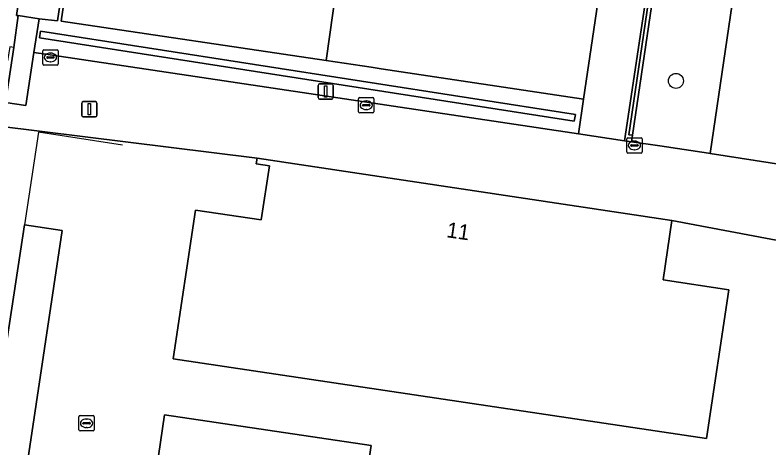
# Model space of a CAD drawing. Extents: x 161090 to 161692, y 379509 to 380907.
# Drawn here: x 161242.72 to 161291.79, y 380401.2 to 380429.41 of the extents above; entities that cross this region are included whole.
import ezdxf

# ---------------------------------------------------------------- set-up
doc = ezdxf.new("R2010")
doc.units = 0
for name, color, linetype in [('IMGEO_Boom', 7, 'Continuous'), ('IMGEO_Groenvoorziening', 7, 'Continuous'), ('IMGEO_Haag', 7, 'Continuous'), ('IMGEO_Kolk', 7, 'Continuous'), ('IMGEO_Lichtmast', 7, 'Continuous'), ('IMGEO_Muur', 7, 'Continuous'), ('IMGEO_Pand', 7, 'Continuous'), ('IMGEO_Pand_nummerreeks', 7, 'Continuous'), ('IMGEO_Rijbaan_lokaal_open', 7, 'Continuous'), ('IMGEO_Terreindeel_halfverhard', 7, 'Continuous'), ('IMGEO_Voetpad_gesloten', 7, 'Continuous'), ('IMGEO_Voetpad_open', 7, 'Continuous')]:
    doc.layers.add(name, color=color, linetype=linetype)

msp = doc.modelspace()

# ---------------------------------------------------------------- linework, layer by layer
at = {"layer": 'IMGEO_Boom'}
msp.add_circle((161285.743, 380425.117), 0.489, dxfattribs=at)
at = {"layer": 'IMGEO_Groenvoorziening'}
for points in [[(161288.546, 380459.846), (161288.807, 380461.604), (161214.037, 380472.701), (161213.983, 380472.328), (161288.498, 380461.269), (161288.271, 380459.723), (161282.68, 380421.608), (161282.918, 380421.573)], [(161244.371, 380428.365), (161244.302, 380427.924), (161279.123, 380422.484), (161279.192, 380422.925)], [(161279.192, 380422.925), (161279.123, 380422.484), (161244.302, 380427.924), (161244.371, 380428.365)], [(161265.895, 380401.354), (161252.452, 380403.361), (161250.511, 380390.143), (161263.942, 380388.053), (161264.811, 380394.143), (161265.201, 380396.75)]]:
    msp.add_lwpolyline(points, close=True, dxfattribs=at)
for points in [[(161242.631, 380427.302), (161242.91, 380429.37), (161242.819, 380429.374), (161248.213, 380465.672)], [(161250.851, 380465.255), (161245.479, 380429.036), (161244.277, 380429.158), (161243.941, 380426.968), (161244.715, 380426.852), (161279.388, 380421.67), (161279.724, 380423.935), (161266.543, 380425.906), (161265.906, 380426.002), (161262.978, 380426.44), (161245.726, 380429.02), (161251.106, 380465.29)], [(161286.723, 380450.172), (161282.385, 380421.222), (161282.856, 380421.152), (161282.918, 380421.573), (161282.68, 380421.608), (161288.271, 380459.723)]]:
    msp.add_lwpolyline(points, dxfattribs=at)
at = {"layer": 'IMGEO_Haag'}
for points in [[(161214.037, 380472.701), (161213.983, 380472.328), (161288.498, 380461.269), (161288.271, 380459.723), (161282.68, 380421.608), (161282.918, 380421.573), (161288.546, 380459.846), (161288.807, 380461.604)], [(161244.371, 380428.365), (161244.302, 380427.924), (161279.123, 380422.484), (161279.192, 380422.925)]]:
    msp.add_lwpolyline(points, close=True, dxfattribs=at)
at = {"layer": 'IMGEO_Kolk'}
for p, q in [((161244.519, 380426.221), (161244.519, 380427.073)), ((161244.594, 380427.147), (161245.446, 380427.147)), ((161245.52, 380427.073), (161245.52, 380426.221)), ((161244.778, 380426.641), (161244.778, 380426.653)), ((161245.216, 380426.604), (161244.818, 380426.604)), ((161244.821, 380426.69), (161245.219, 380426.69)), ((161245.007, 380426.927), (161245.032, 380426.927)), ((161245.262, 380426.653), (161245.262, 380426.641)), ((161245.446, 380426.147), (161244.594, 380426.147)), ((161245.03, 380426.367), (161245.005, 380426.367)), ((161265.153, 380424.03), (161266.005, 380424.03)), ((161265.078, 380423.104), (161265.078, 380423.956)), ((161265.337, 380423.524), (161265.337, 380423.536)), ((161265.38, 380423.573), (161265.778, 380423.573)), ((161265.566, 380423.81), (161265.591, 380423.81)), ((161265.821, 380423.536), (161265.821, 380423.524)), ((161266.079, 380423.956), (161266.079, 380423.104)), ((161266.005, 380423.03), (161265.153, 380423.03)), ((161265.775, 380423.487), (161265.377, 380423.487)), ((161265.589, 380423.25), (161265.564, 380423.25)), ((161282.541, 380420.488), (161282.541, 380421.34)), ((161282.616, 380421.414), (161283.468, 380421.414)), ((161283.029, 380421.194), (161283.054, 380421.194)), ((161283.542, 380421.34), (161283.542, 380420.488)), ((161282.8, 380420.908), (161282.8, 380420.92)), ((161283.238, 380420.871), (161282.84, 380420.871)), ((161282.843, 380420.957), (161283.241, 380420.957)), ((161283.052, 380420.634), (161283.027, 380420.634)), ((161283.284, 380420.92), (161283.284, 380420.908)), ((161283.468, 380420.414), (161282.616, 380420.414)), ((161246.868, 380402.38), (161246.868, 380403.232)), ((161246.943, 380403.306), (161247.795, 380403.306)), ((161247.356, 380403.086), (161247.381, 380403.086)), ((161247.869, 380403.232), (161247.869, 380402.38)), ((161247.127, 380402.8), (161247.127, 380402.812)), ((161247.565, 380402.763), (161247.167, 380402.763)), ((161247.17, 380402.849), (161247.568, 380402.849)), ((161247.379, 380402.526), (161247.354, 380402.526)), ((161247.611, 380402.812), (161247.611, 380402.8)), ((161247.795, 380402.306), (161246.943, 380402.306))]:
    msp.add_line(p, q, dxfattribs=at)
for points in [[(161244.519, 380426.221), (161244.519, 380427.073)], [(161244.594, 380427.147), (161245.446, 380427.147)], [(161245.52, 380427.073), (161245.52, 380426.221)], [(161245.446, 380426.147), (161244.594, 380426.147)], [(161265.153, 380424.03), (161266.005, 380424.03)], [(161265.078, 380423.104), (161265.078, 380423.956)], [(161266.079, 380423.956), (161266.079, 380423.104)], [(161266.005, 380423.03), (161265.153, 380423.03)], [(161282.541, 380420.488), (161282.541, 380421.34)], [(161282.616, 380421.414), (161283.468, 380421.414)], [(161283.542, 380421.34), (161283.542, 380420.488)], [(161283.468, 380420.414), (161282.616, 380420.414)], [(161246.868, 380402.38), (161246.868, 380403.232)], [(161246.943, 380403.306), (161247.795, 380403.306)], [(161247.869, 380403.232), (161247.869, 380402.38)], [(161247.795, 380402.306), (161246.943, 380402.306)]]:
    msp.add_lwpolyline(points, dxfattribs=at)
for centre, radius, start, end in [((161244.596, 380427.071), 0.0765, 91.552, 178.448), ((161244.596, 380427.071), 0.0765, 91.552, 178.448), ((161245.444, 380427.071), 0.0765, 1.552, 88.448), ((161245.444, 380427.071), 0.0765, 1.552, 88.448), ((161244.818, 380426.65), 0.0403, 85.8775, 175.7526), ((161244.815, 380426.64), 0.0366, 178.938, 274.7102), ((161245.219, 380426.647), 0.043, 264.8664, 352.4533), ((161245.223, 380426.652), 0.0386, 1.7309, 96.639), ((161244.596, 380426.223), 0.0765, 181.552, 268.448), ((161244.596, 380426.223), 0.0765, 181.552, 268.448), ((161245.444, 380426.223), 0.0765, 271.552, 358.448), ((161245.444, 380426.223), 0.0765, 271.552, 358.448), ((161265.155, 380423.954), 0.0765, 91.552, 178.448), ((161265.155, 380423.954), 0.0765, 91.552, 178.448), ((161266.003, 380423.954), 0.0765, 1.552, 88.448), ((161266.003, 380423.954), 0.0765, 1.552, 88.448), ((161265.377, 380423.533), 0.0403, 85.8775, 175.7526), ((161265.374, 380423.523), 0.0366, 178.938, 274.7102), ((161265.778, 380423.53), 0.043, 264.8664, 352.4533), ((161265.782, 380423.535), 0.0386, 1.7309, 96.639), ((161265.155, 380423.106), 0.0765, 181.552, 268.448), ((161265.155, 380423.106), 0.0765, 181.552, 268.448), ((161266.003, 380423.106), 0.0765, 271.552, 358.448), ((161266.003, 380423.106), 0.0765, 271.552, 358.448), ((161282.618, 380421.338), 0.0765, 91.552, 178.448), ((161282.618, 380421.338), 0.0765, 91.552, 178.448), ((161283.466, 380421.338), 0.0765, 1.552, 88.448), ((161283.466, 380421.338), 0.0765, 1.552, 88.448), ((161282.84, 380420.917), 0.0403, 85.8775, 175.7526), ((161282.837, 380420.907), 0.0366, 178.938, 274.7102), ((161283.241, 380420.914), 0.043, 264.8664, 352.4533), ((161283.245, 380420.919), 0.0386, 1.7309, 96.639), ((161282.618, 380420.49), 0.0765, 181.552, 268.448), ((161282.618, 380420.49), 0.0765, 181.552, 268.448), ((161283.466, 380420.49), 0.0765, 271.552, 358.448), ((161283.466, 380420.49), 0.0765, 271.552, 358.448), ((161246.945, 380403.23), 0.0765, 91.552, 178.448), ((161246.945, 380403.23), 0.0765, 91.552, 178.448), ((161247.793, 380403.23), 0.0765, 1.552, 88.448), ((161247.793, 380403.23), 0.0765, 1.552, 88.448), ((161247.167, 380402.809), 0.0403, 85.8775, 175.7526), ((161247.164, 380402.799), 0.0366, 178.938, 274.7102), ((161247.568, 380402.806), 0.043, 264.8664, 352.4533), ((161247.572, 380402.811), 0.0386, 1.7309, 96.639), ((161246.945, 380402.382), 0.0765, 181.552, 268.448), ((161246.945, 380402.382), 0.0765, 181.552, 268.448), ((161247.793, 380402.382), 0.0765, 271.552, 358.448), ((161247.793, 380402.382), 0.0765, 271.552, 358.448)]:
    msp.add_arc(centre, radius, start, end, dxfattribs=at)
for centre, major_axis, ratio, start_param, end_param in [((161245.006, 380426.647), (-0.387, 0.002), 0.722429, 4.712389, 7.853982), ((161245.031, 380426.647), (-0.39, 0.002), 0.717154, 1.570796, 4.712389), ((161265.565, 380423.53), (-0.387, 0.002), 0.722429, 4.712389, 7.853982), ((161265.59, 380423.53), (-0.39, 0.002), 0.717154, 1.570796, 4.712389), ((161283.028, 380420.914), (-0.387, 0.002), 0.722429, 4.712389, 7.853982), ((161283.053, 380420.914), (-0.39, 0.002), 0.717154, 1.570796, 4.712389), ((161247.355, 380402.806), (-0.387, 0.002), 0.722429, 4.712389, 7.853982), ((161247.38, 380402.806), (-0.39, 0.002), 0.717154, 1.570796, 4.712389)]:
    msp.add_ellipse(centre, major_axis=major_axis, ratio=ratio, start_param=start_param, end_param=end_param, dxfattribs=at)
at = {"layer": 'IMGEO_Lichtmast'}
for p, q in [((161262.443, 380424.026), (161262.443, 380424.826)), ((161262.443, 380424.826), (161262.443, 380424.026)), ((161262.543, 380424.926), (161263.333, 380424.926)), ((161263.333, 380424.926), (161262.543, 380424.926)), ((161263.433, 380424.826), (161263.433, 380424.026)), ((161263.433, 380424.026), (161263.433, 380424.826)), ((161247.057, 380422.872), (161247.057, 380423.672)), ((161247.057, 380423.672), (161247.057, 380422.872)), ((161247.157, 380423.772), (161247.947, 380423.772)), ((161247.947, 380423.772), (161247.157, 380423.772)), ((161248.047, 380423.672), (161248.047, 380422.872)), ((161248.047, 380422.872), (161248.047, 380423.672)), ((161263.333, 380423.926), (161262.543, 380423.926)), ((161262.543, 380423.926), (161263.333, 380423.926)), ((161247.947, 380422.772), (161247.157, 380422.772)), ((161247.157, 380422.772), (161247.947, 380422.772))]:
    msp.add_line(p, q, dxfattribs=at)
for points in [[(161262.863, 380424.801), (161263.013, 380424.801), (161263.013, 380424.051), (161262.863, 380424.051), (161262.863, 380424.801)], [(161247.477, 380423.647), (161247.627, 380423.647), (161247.627, 380422.897), (161247.477, 380422.897), (161247.477, 380423.647)]]:
    msp.add_lwpolyline(points, dxfattribs=at)
for centre, start, end in [((161262.543, 380424.826), 90, 180), ((161262.543, 380424.826), 90, 180), ((161263.333, 380424.826), 0, 90), ((161263.333, 380424.826), 360, 90), ((161262.543, 380424.026), 180, 270), ((161262.543, 380424.026), 180, 270), ((161263.333, 380424.026), 270, 0), ((161263.333, 380424.026), 270, 0), ((161247.157, 380423.672), 90, 180), ((161247.157, 380423.672), 90, 180), ((161247.947, 380423.672), 0, 90), ((161247.947, 380423.672), 360, 90), ((161247.157, 380422.872), 180, 270), ((161247.157, 380422.872), 180, 270), ((161247.947, 380422.872), 270, 0), ((161247.947, 380422.872), 270, 0)]:
    msp.add_arc(centre, 0.1, start, end, dxfattribs=at)
at = {"layer": 'IMGEO_Muur'}
for points in [[(161249.702, 380420.931), (161244.232, 380421.774), (161243.32, 380415.746)], [(161243.32, 380415.746), (161240.065, 380394.451), (161249.42, 380393.066)]]:
    msp.add_lwpolyline(points, dxfattribs=at)
at = {"layer": 'IMGEO_Pand'}
msp.add_lwpolyline([(161258.474, 380420.084), (161258.419, 380419.717), (161259.279, 380419.589), (161258.746, 380416.059), (161254.463, 380416.699), (161252.998, 380407.005), (161287.733, 380401.815), (161289.192, 380411.506), (161284.9, 380412.152), (161285.472, 380416.02)], close=True, dxfattribs=at)
at = {"layer": 'IMGEO_Rijbaan_lokaal_open'}
msp.add_lwpolyline([(161298.54, 380457.978), (161298.672, 380458.755), (161298.836, 380459.875), (161299.94, 380467.397), (161294.974, 380468.152), (161293.861, 380460.549), (161293.673, 380459.266), (161287.966, 380420.387), (161292.846, 380419.624)], close=True, dxfattribs=at)
at = {"layer": 'IMGEO_Terreindeel_halfverhard'}
for points in [[(161268.065, 380462.727), (161251.106, 380465.29), (161245.726, 380429.02), (161262.978, 380426.44)], [(161283.675, 380450.607), (161285.098, 380460.152), (161272.314, 380462.084), (161271.45, 380462.215), (161268.065, 380462.727), (161262.978, 380426.44), (161265.906, 380426.002), (161266.543, 380425.906), (161279.724, 380423.935)]]:
    msp.add_lwpolyline(points, close=True, dxfattribs=at)
at = {"layer": 'IMGEO_Voetpad_gesloten'}
msp.add_lwpolyline([(161249.42, 380393.066), (161249.74, 380395.447), (161242.932, 380396.362), (161245.791, 380415.367), (161243.32, 380415.746), (161240.065, 380394.451)], close=True, dxfattribs=at)
at = {"layer": 'IMGEO_Voetpad_open'}
for points in [[(161244.277, 380429.158), (161245.479, 380429.036), (161250.851, 380465.255), (161248.213, 380465.672), (161242.819, 380429.374), (161242.91, 380429.37)], [(161293.673, 380459.266), (161288.546, 380459.846), (161282.918, 380421.573), (161282.856, 380421.152), (161284.692, 380420.877), (161287.86, 380420.404), (161287.966, 380420.387)], [(161283.675, 380450.607), (161279.724, 380423.935), (161279.388, 380421.67), (161282.385, 380421.222), (161286.723, 380450.172)], [(161242.91, 380429.37), (161242.631, 380427.302), (161242.088, 380423.717), (161243.412, 380423.518), (161243.941, 380426.968), (161244.277, 380429.158)], [(161240.065, 380394.451), (161243.32, 380415.746), (161245.791, 380415.367), (161242.932, 380396.362), (161249.74, 380395.447), (161249.42, 380393.066)]]:
    msp.add_lwpolyline(points, close=True, dxfattribs=at)
for points in [[(161292.846, 380419.624), (161287.966, 380420.387), (161287.86, 380420.404), (161284.692, 380420.877), (161282.856, 380421.152), (161282.385, 380421.222), (161279.388, 380421.67), (161244.715, 380426.852), (161243.941, 380426.968), (161243.412, 380423.518), (161242.088, 380423.717), (161242.631, 380427.302), (161242.374, 380427.337), (161242.228, 380426.436), (161242.131, 380426.443), (161241.913, 380424.971), (161241.495, 380422.179), (161258.474, 380420.084), (161285.472, 380416.02), (161295.711, 380414.078)], [(161292.877, 380394.986), (161295.711, 380414.078), (161285.472, 380416.02), (161284.9, 380412.152), (161289.192, 380411.506), (161287.733, 380401.815), (161252.998, 380407.005), (161254.463, 380416.699), (161258.746, 380416.059), (161259.279, 380419.589), (161258.419, 380419.717), (161258.474, 380420.084), (161241.495, 380422.179), (161236.726, 380390.707)], [(161250.511, 380390.143), (161252.452, 380403.361), (161265.895, 380401.354), (161265.201, 380396.75)]]:
    msp.add_lwpolyline(points, dxfattribs=at)

# ---------------------------------------------------------------- texts
at = {"layer": 'IMGEO_Pand_nummerreeks'}
msp.add_text('11', height=1, rotation=351.7815, dxfattribs=at).set_placement((161270.762, 380414.938))

doc.saveas('drawing.dxf')
